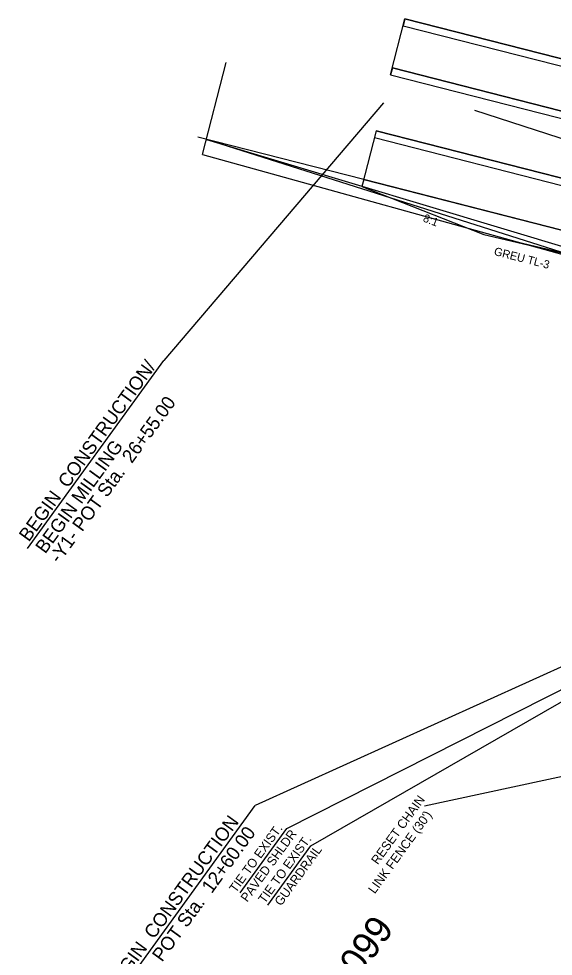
# Model space of a CAD drawing. Extents: x 1183930 to 1185370, y 573068 to 574871.
# Drawn here: x 1183930 to 1184226, y 573705 to 574224 of the extents above; entities that cross this region are included whole.
import ezdxf

# ---------------------------------------------------------------- set-up
doc = ezdxf.new("R2010")
doc.units = 0
for name, color, linetype in [('E_NCDOT_Vertical_Profile_Ground_Line', 7, 'Continuous'), ('P_NCDOT_Horizontal_Alignment', 7, 'Continuous'), ('P_NCDOT_Horizontal_Alignment_Tick_Small', 7, 'Continuous'), ('P_NCDOT_Vertical_Profile_Ditch_Grade_Left', 7, 'Continuous'), ('PC_OBJECT', 7, 'Continuous'), ('PC_PADFOOTING', 7, 'Continuous'), ('PS_HATCH', 7, 'Continuous')]:
    doc.layers.add(name, color=color, linetype=linetype)

msp = doc.modelspace()

# ---------------------------------------------------------------- linework, layer by layer
at = {"layer": 'E_NCDOT_Vertical_Profile_Ground_Line'}
for p, q in [((1184144.08, 574224.27), (1184371.09, 574166.16)), ((1184144.08, 574224.27), (1184290.79, 574186.71)), ((1184136.14, 574193.27), (1184503.1, 574099.33)), ((1184136.14, 574193.27), (1184503.1, 574099.33)), ((1184136.14, 574193.27), (1184503.1, 574099.33)), ((1184128.2, 574162.27), (1184495.16, 574068.33)), ((1184128.2, 574162.27), (1184495.16, 574068.33)), ((1184128.2, 574162.27), (1184495.16, 574068.33)), ((1184120.27, 574131.27), (1184187.79, 574104.7)), ((1184187.79, 574104.7), (1184236.47, 574093.27))]:
    msp.add_line(p, q, dxfattribs=at)
at = {"layer": 'P_NCDOT_Horizontal_Alignment'}
for p, q in [((1184136.14, 574193.27), (1184144.08, 574224.27)), ((1184143.08, 574220.4), (1184971.37, 574008.35)), ((1184143.08, 574220.4), (1184977.73, 574006.73)), ((1184031.97, 574149), (1184045.02, 574199.98)), ((1184137.13, 574197.15), (1184965.42, 573985.1)), ((1184137.13, 574197.15), (1184971.78, 573983.48)), ((1184121.26, 574135.15), (1184029.29, 574158.69)), ((1184034.09, 574157.29), (1184427, 574039.4)), ((1184432.78, 574030.72), (1184034.09, 574157.29)), ((1184128.2, 574162.27), (1184120.27, 574131.27)), ((1184127.21, 574158.4), (1184955.5, 573946.35)), ((1184127.21, 574158.4), (1184961.86, 573944.73)), ((1184031.97, 574149), (1184432.31, 574037.93)), ((1184121.26, 574135.15), (1184949.55, 573923.1)), ((1184121.26, 574135.15), (1184955.9, 573921.48))]:
    msp.add_line(p, q, dxfattribs=at)
at = {"layer": 'P_NCDOT_Horizontal_Alignment_Tick_Small'}
msp.add_line((1184236.47, 574093.27), (1184199.75, 574101.89), dxfattribs=at)
at = {"layer": 'P_NCDOT_Vertical_Profile_Ditch_Grade_Left'}
msp.add_lwpolyline([(1184400.58, 574113.19), (1184250.03, 574151.73), (1184182.69, 574173.53)], dxfattribs=at)
at = {"layer": 'PC_OBJECT'}
for p, q in [((1184144.08, 574224.27), (1184143.08, 574220.4)), ((1184143.08, 574220.4), (1184547.76, 574116.8)), ((1184290.79, 574186.71), (1184144.08, 574224.27)), ((1184137.13, 574197.15), (1184136.14, 574193.27)), ((1184136.14, 574193.27), (1184503.1, 574099.33)), ((1184128.2, 574162.27), (1184127.21, 574158.4)), ((1184127.21, 574158.4), (1184507.42, 574061.06)), ((1184495.16, 574068.33), (1184128.2, 574162.27))]:
    msp.add_line(p, q, dxfattribs=at)
msp.add_lwpolyline([(1184532.63, 574095.9), (1184476.98, 574110.15), (1184137.13, 574197.15)], dxfattribs=at)
msp.add_lwpolyline([(1184432.95, 574039.87), (1184482.84, 574027.1), (1184492.29, 574040.16), (1184121.26, 574135.15), (1184120.27, 574131.27), (1184187.79, 574104.7), (1184236.47, 574093.27), (1184268.26, 574085.13), (1184407.93, 574046.38), (1184408.48, 574048.54), (1184433.66, 574042.1)], close=True, dxfattribs=at)
at = {"layer": 'PC_PADFOOTING'}
for p, q in [((1184078.72, 573775.62), (1184271.5, 573873.22)), ((1184091.98, 573766.03), (1184267.65, 573867.08)), ((1184154.9, 573788.2), (1184241.05, 573806.78)), ((1184068.2, 573733.26), (1184091.98, 573766.03))]:
    msp.add_line(p, q, dxfattribs=at)
msp.add_lwpolyline([(1184052.84, 573739.95), (1184078.72, 573775.62)], dxfattribs=at)
at = {"layer": 'PS_HATCH'}
for p, q in [((1184132.17, 574177.77), (1184010.49, 574035.03)), ((1183934.9, 573930.86), (1184010.49, 574035.03)), ((1184280.64, 573887.8), (1184061.17, 573788.33)), ((1183984.72, 573682.95), (1184061.17, 573788.33))]:
    msp.add_line(p, q, dxfattribs=at)

# ---------------------------------------------------------------- texts
at = {"layer": 'PC_PADFOOTING'}
for s, height, rotation, p in [('8:1', 4.5, 338.5714, (1184153.7, 574112.12)), ('RESET CHAIN', 5, 54.0376, (1184129.01, 573755.29)), ("LINK FENCE (30')", 5, 54.0376, (1184127.33, 573739.14)), ('TIE TO EXIST.', 5, 54.0376, (1184050.39, 573739.7)), ('PAVED SHLDR', 5, 54.0376, (1184056.7, 573734.56)), ('TIE TO EXIST.', 5, 54.0376, (1184066.41, 573733.75)), ('GUARDRAIL', 5, 54.0376, (1184075.46, 573732.4))]:
    msp.add_text(s, height=height, rotation=rotation, dxfattribs=at).set_placement(p)
at = {"layer": 'PS_HATCH'}
for s, height, rotation, p in [('GREU TL-3', 4.5, 345.6405, (1184193.06, 574093.46)), ('BEGIN  CONSTRUCTION/', 7.5, 54.0376, (1183935.72, 573934.07)), ('-Y1- POT Sta.  26+55.00', 7.5, 54.0376, (1183952.51, 573922.07)), ('BEGIN MILLING', 7.5, 54.0376, (1183944.82, 573927.46)), ('BEGIN  CONSTRUCTION', 7.5, 54.0376, (1183983.41, 573684.22)), ('-RPC- POT Sta.  12+60.00', 7.5, 54.0376, (1183991.5, 573676.53)), ('BEGIN TIP PROJECT BR-0099', 15, 54.0376, (1183972.25, 573490.87))]:
    msp.add_text(s, height=height, rotation=rotation, dxfattribs=at).set_placement(p)

doc.saveas('drawing.dxf')
